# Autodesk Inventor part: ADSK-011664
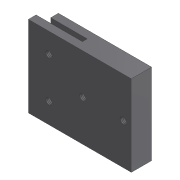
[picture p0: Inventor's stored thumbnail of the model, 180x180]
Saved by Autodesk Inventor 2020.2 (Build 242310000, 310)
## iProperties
Created: 2000-02
Part Number: ADSK-011664
Document SubType Name: Modeling
Description: PLT-04,FH,AX,05,025,020,CCCC,CLAMP BLOCK
Designer: lnowak
Material: Acier doux
Density: 7.86 g/cm^3
Appearance: Metal-Steel(Polish)
Mass: 261.64 g
Surface Area: 116.263 cm^2
Volume: 33.2875 cm^3
Control State: 0
Checked Out: False
Master: False
Shininess: 60.0
Length Units: 11269
Angle Units: 11279
Time Units: 11290
Mass Units: 11283
Length Display Precision: 3
Angle Display Precision: 2
Compacted: True
Cutlength: 2.5
Material Desc: FLAT,HRS,0.500X02.000
Material_Number: A084313
Dimensions: 50x12,5x63,5 mm
Mass: 0,262 kg
VLT_Material: Acier doux
Density: 7.86
Volumn: 33.63531228437358
Area: 118.11549903845408
PropertySet Name: Model Information
Author: lnowak
Revision Number: -
Title: PLT-04,FH,AX,05,025,020,CCCC,CLAMP BLOCK
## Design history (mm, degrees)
node "Extrusion1" dims "d2" = 12.5, "d3" = 0
  sketch "Sketch1"
    geometry: L1 (-31.75, -25)-(31.75, -25); L2 (31.75, -25)-(31.75, 25); L3 (31.75, 25)-(-31.75, 25); L4 (-31.75, 25)-(-31.75, -25); 3 further points
    constraints: 8 end point, 2 midpoint, 2 parallel, 1 horizontal, 1 horizontal alignment, 1 perpendicular, 1 vertical alignment
    dimensions: "d0" = 63.5 distance of L2.end L3.end; "d1" = 50 distance of L1.end L2.end
node "Extrusion2" dims "d23" = 28.575, "d24" = 0
  sketch "Sketch3"
    geometry: L1 (4.75, 50)-(7.75, 50); L2 (4.75, 0)-(7.75, 0); L3 (7.75, 50)-(7.75, 0); L4 (4.75, 50)-(4.75, 0); L5 (0, 0)-(12.5, 0) reference; L6 (0, 50)-(12.5, 50) reference; 1 further point
    constraints: 8 end point, 3 perpendicular, 2 collinear, 2 midpoint, 1 parallel
    dimensions: "d20" = 3 distance between parallel lines of L4 L3
node "Hole1" dims "d10" = 4.134, "d11" = 9.525, "d12" = 6.35, "d13" = 60 deg, "d14" = 14.2, "d15" = 118 deg, "d33" = 10
  sketch "Sketch2"
    geometry: L1 (31.75, 25)-(31.75, -25) reference; L2 (-19.175, 12.5)-(-19.175, -12.5); L3 (1.75, 0)-(26.75, 0); L4 (-31.75, -25)-(-31.75, 25) reference; L5 (-3.175, 25)-(-3.175, -25) reference; 3 further points
    constraints: 4 end point, 3 horizontal alignment, 3 midpoint, 1 horizontal, 1 vertical, 1 vertical alignment
    dimensions: "d29" = 25 distance of L3.start L3.end; "d30" = 5 distance from line of L1 L3.end; "d31" = 25 distance of L2.start L2.end; "d41" = 16 distance between parallel lines of L5 L2
node "Extrusion3" dims "d27" = 28.575, "d28" = 0
  sketch "Sketch4"
    geometry: L1 (31.75, -25)-(25.75, -25); L2 (31.75, 25)-(31.75, -25); L3 (25.75, 25)-(31.75, 25); L4 (25.75, 25)-(25.75, -25); L5 (-31.75, 25)-(31.75, 25) reference; L6 (31.75, -25)-(-31.75, -25) reference; L7 (31.75, 25)-(31.75, -25) reference
    constraints: 8 end point, 3 collinear, 1 perpendicular
    dimensions: "d25" = 6 distance between parallel lines of L4 L2
sketch "Skizze5"
  geometry: C1 r 2.067 at (19.175, -12.5) reference; C2 r 2.067 at (19.175, 12.5) reference; 1 further point
hole "Bohrung2" sketch "Skizze5" at (19.175, -12.5), (19.175, 12.5) diameter "d34" = 5.5; stored, may be unused: countersink angle "d38" = 90 deg, drill point angle "d40" = 118 deg; dims "d35" = 10, "d36" = 10.4, "d37" = 2, "d39" = 14.2
node "Solide1"
node "Corps solides"
node "Corps surfaciques"
